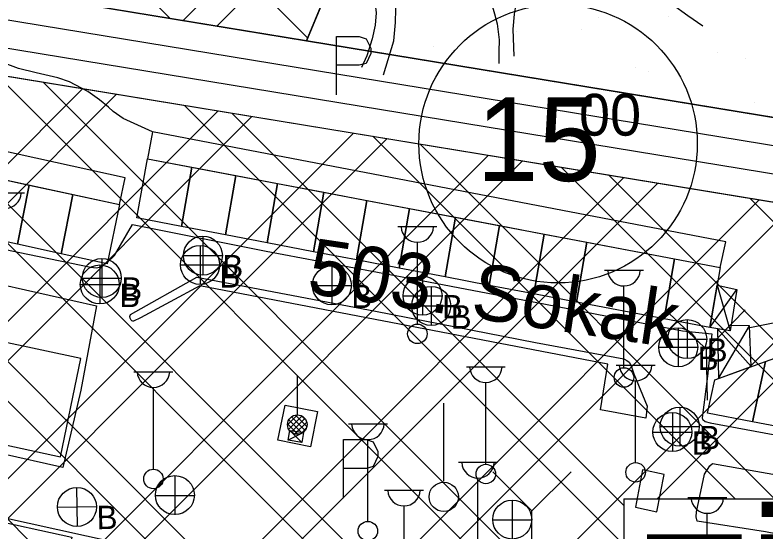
# Model space of a CAD drawing. Extents: x 417995 to 421451, y 4454518 to 4458015.
# Drawn here: x 419824.7 to 419959.6, y 4456060.9 to 4456153.7 of the extents above; entities that cross this region are included whole.
import ezdxf

# ---------------------------------------------------------------- set-up
doc = ezdxf.new("R2010")
doc.units = 0
for name, color, linetype in [('ADAKENARI', 7, 'Continuous'), ('B_Imalat', 7, 'Continuous'), ('B_Sundurma', 7, 'Continuous'), ('KALDIRIM_FAT', 7, 'Continuous'), ('KD_DAIRE', 7, 'Continuous'), ('KD_YGEN', 7, 'Continuous'), ('PL_AYA_PARK_DINLENME', 7, 'Continuous'), ('PL_K_DEPOLAMA', 7, 'Continuous'), ('PL_TOPLU_ISYERI', 7, 'Continuous'), ('S_Bayrak_Diregi', 7, 'Continuous'), ('S_Cad_Sok_Lambasi', 7, 'Continuous'), ('S_GSM_Baz_ist', 7, 'Continuous'), ('S_Otopark', 7, 'Continuous'), ('S_Rogar_Kapagi', 7, 'Continuous'), ('S_Rogar_Kapagi_Buski', 7, 'Continuous'), ('S_Yangin_Vanasi', 7, 'Continuous'), ('Sinir_Tel_bir_taraf', 7, 'Continuous'), ('TRFAT_DEPOLAMA', 7, 'Continuous'), ('TRFAT_PARKALANI', 7, 'Continuous'), ('TRFAT_TOPLUİŞYERLERİ', 7, 'Continuous'), ('Y_Cadde_Yol', 7, 'Continuous'), ('Yol_Kaldirim_kenari_bordurtasi', 7, 'Continuous'), ('Yol_Sose', 7, 'Continuous')]:
    doc.layers.add(name, color=color, linetype=linetype)

msp = doc.modelspace()

# ---------------------------------------------------------------- linework, layer by layer
at = {"layer": 'ADAKENARI'}
for p, q in [((419877.03, 4456149.07), (419946.16, 4456314.89)), ((419776.06, 4456165.64), (419877.03, 4456149.07)), ((419771.34, 4456151.21), (420017.31, 4456110.85)), ((419877.03, 4456149.07), (419969.35, 4456133.92))]:
    msp.add_line(p, q, dxfattribs=at)
at = {"layer": 'B_Imalat'}
for points in [[(419843.42, 4456119.65), (419844.44, 4456124.45), (419796.82, 4456134.91), (419795.72, 4456129.95)], [(419951.33, 4456108.35), (419952.36, 4456112.94), (419849.37, 4456132.69), (419848.49, 4456127.88)], [(419848.49, 4456127.88), (419856.44, 4456126.38), (419854.6, 4456115.71), (419846.53, 4456117.26)], [(419856.44, 4456126.38), (419864.32, 4456124.88), (419862.48, 4456114.21), (419854.6, 4456115.71)], [(419819.3, 4456124.85), (419827.21, 4456123.15), (419825.1, 4456112.52), (419817.19, 4456114.24)], [(419864.32, 4456124.88), (419871.81, 4456123.46), (419869.97, 4456112.77), (419862.48, 4456114.21)], [(419827.21, 4456123.15), (419835.07, 4456121.45), (419832.95, 4456110.81), (419825.1, 4456112.52)], [(419871.81, 4456123.46), (419880.12, 4456121.88), (419878.28, 4456111.19), (419869.97, 4456112.77)], [(419880.12, 4456121.88), (419887.86, 4456120.41), (419886.01, 4456109.71), (419878.28, 4456111.19)], [(419835.07, 4456121.45), (419843.42, 4456119.65), (419841.25, 4456109), (419832.95, 4456110.81)], [(419887.86, 4456120.41), (419895.54, 4456118.95), (419893.69, 4456108.24), (419886.01, 4456109.71)], [(419895.54, 4456118.95), (419903.77, 4456117.38), (419901.92, 4456106.66), (419893.69, 4456108.24)], [(419903.77, 4456117.38), (419911.72, 4456115.88), (419909.86, 4456105.15), (419901.92, 4456106.66)], [(419911.72, 4456115.88), (419919.69, 4456114.36), (419917.84, 4456103.62), (419909.86, 4456105.15)], [(419919.69, 4456114.36), (419927.38, 4456112.9), (419925.53, 4456102.15), (419917.84, 4456103.62)], [(419927.38, 4456112.9), (419943.13, 4456109.91), (419941.27, 4456099.14), (419925.53, 4456102.15)], [(419943.13, 4456109.91), (419951.33, 4456108.35), (419949.47, 4456097.57), (419941.27, 4456099.14)], [(419957.13, 4456080.66), (419959.5, 4456091.5), (419967.65, 4456094.44), (419966.93, 4456089.9), (419967.35, 4456089.82), (419965.02, 4456079.14)], [(419949.06, 4456082.23), (419950.37, 4456088.21), (419959.5, 4456091.5), (419957.13, 4456080.66)], [(419818.97, 4456063.44), (419834.88, 4456059.95), (419832.71, 4456049.03), (419816.79, 4456052.47)]]:
    msp.add_lwpolyline(points, close=True, dxfattribs=at)
at = {"layer": 'B_Sundurma'}
for p, q in [((419949.47, 4456097.57), (419954.33, 4456104.39)), ((419950.78, 4456105.17), (419953.1, 4456097.01)), ((419951.05, 4456088.46), (419956.62, 4456097.87)), ((419950.85, 4456097.36), (419956.91, 4456090.57)), ((419876.49, 4456078.71), (419873.75, 4456077.35)), ((419874.05, 4456079.12), (419876.19, 4456076.94))]:
    msp.add_line(p, q, dxfattribs=at)
for points in [[(419949.47, 4456097.57), (419950.78, 4456105.17), (419954.33, 4456104.39), (419953.1, 4456097.01)], [(419950.85, 4456097.36), (419951.05, 4456088.46), (419956.91, 4456090.57), (419956.62, 4456097.87), (419953.25, 4456097.92), (419953.1, 4456097.01)], [(419874.05, 4456079.12), (419876.49, 4456078.71), (419876.19, 4456076.94), (419873.75, 4456077.35)]]:
    msp.add_lwpolyline(points, close=True, dxfattribs=at)
at = {"layer": 'KALDIRIM_FAT'}
for p, q in [((419764.54, 4456162.46), (420016.91, 4456121.05)), ((419762.96, 4456157.65), (420017.11, 4456115.95))]:
    msp.add_line(p, q, dxfattribs=at)
at = {"layer": 'KD_DAIRE'}
msp.add_circle((419922.22, 4456130.58), 25, dxfattribs=at)
at = {"layer": 'PL_AYA_PARK_DINLENME'}
msp.add_lwpolyline([(419877.03, 4456149.07), (419946.16, 4456314.89), (419962.3, 4456307.28), (419997.77, 4456307.14), (419969.35, 4456133.92)], close=True, dxfattribs=at)
at = {"layer": 'PL_K_DEPOLAMA'}
msp.add_lwpolyline([(419774.25, 4456168.89), (419852.21, 4456355.88), (419856.08, 4456357.37), (419946.16, 4456314.89), (419877.03, 4456149.07), (419776.06, 4456165.64)], close=True, dxfattribs=at)
at = {"layer": 'PL_TOPLU_ISYERI'}
msp.add_lwpolyline([(419771.34, 4456151.21), (420017.31, 4456110.85)], dxfattribs=at)
at = {"layer": 'S_Bayrak_Diregi'}
msp.add_line((419901.67, 4456070.01), (419901.67, 4456084.01), dxfattribs=at)
msp.add_circle((419901.68, 4456067.19), 2.63, dxfattribs=at)
at = {"layer": 'S_Cad_Sok_Lambasi'}
for p, q in [((419819.37, 4456121.78), (419826.37, 4456121.78)), ((419893.44, 4456115.7), (419900.44, 4456115.7)), ((419896.94, 4456098.2), (419896.94, 4456112.88)), ((419930.55, 4456107.86), (419937.55, 4456107.86)), ((419934.05, 4456090.36), (419934.05, 4456105.04)), ((419932.64, 4456090.84), (419939.64, 4456090.84)), ((419846.03, 4456089.65), (419853.03, 4456089.65)), ((419905.74, 4456090.54), (419912.74, 4456090.54)), ((419936.14, 4456073.34), (419936.14, 4456088.01)), ((419849.53, 4456072.15), (419849.53, 4456086.82)), ((419909.24, 4456073.04), (419909.24, 4456087.71)), ((419884.55, 4456080.29), (419891.55, 4456080.29)), ((419888.05, 4456062.79), (419888.05, 4456077.46)), ((419904.33, 4456073.39), (419911.33, 4456073.39)), ((419907.83, 4456055.89), (419907.83, 4456070.57)), ((419891.04, 4456068.39), (419898.04, 4456068.39)), ((419945.51, 4456067.05), (419952.51, 4456067.05)), ((419894.54, 4456050.89), (419894.54, 4456065.56)), ((419949.01, 4456049.55), (419949.01, 4456064.23))]:
    msp.add_line(p, q, dxfattribs=at)
for centre in [(419896.94, 4456096.45), (419934.05, 4456088.61), (419936.14, 4456071.59), (419849.53, 4456070.4), (419909.24, 4456071.29), (419888.05, 4456061.04)]:
    msp.add_circle(centre, 1.75, dxfattribs=at)
for centre in [(419822.87, 4456121.88), (419896.94, 4456115.81), (419934.05, 4456107.97), (419936.14, 4456090.94), (419849.53, 4456089.75), (419909.24, 4456090.64), (419888.05, 4456080.39), (419907.83, 4456073.5), (419894.54, 4456068.49), (419949.01, 4456067.16)]:
    msp.add_arc(centre, 2.93, 183.298, 356.9072, dxfattribs=at)
at = {"layer": 'S_GSM_Baz_ist'}
for p, q in [((419875.38, 4456081.89), (419875.38, 4456088.89)), ((419873.63, 4456080.14), (419875.41, 4456081.89)), ((419873.84, 4456079.33), (419876.18, 4456081.68)), ((419876.78, 4456079.09), (419874.33, 4456081.54)), ((419877.06, 4456079.79), (419875.03, 4456081.85)), ((419876.95, 4456080.87), (419876.11, 4456081.71)), ((419875.45, 4456078.42), (419873.66, 4456080.24)), ((419876.22, 4456078.63), (419873.87, 4456081.01)), ((419874.29, 4456078.81), (419876.71, 4456081.26)), ((419874.96, 4456078.49), (419877.06, 4456080.59)), ((419876.04, 4456078.56), (419876.95, 4456079.51))]:
    msp.add_line(p, q, dxfattribs=at)
msp.add_circle((419875.37, 4456080.16), 1.75, dxfattribs=at)
at = {"layer": 'S_Otopark'}
for points in [[(419882.41, 4456149.83), (419886.51, 4456149.83)], [(419882.41, 4456139.33), (419882.41, 4456149.83)], [(419886.51, 4456149.83), (419887.73, 4456149.41), (419888.57, 4456147.7), (419888.57, 4456146.79), (419887.73, 4456145), (419886.51, 4456144.65)], [(419886.51, 4456144.65), (419882.41, 4456144.65)], [(419883.68, 4456077.48), (419887.78, 4456077.48)], [(419883.68, 4456066.98), (419883.68, 4456077.48)], [(419887.78, 4456077.48), (419889, 4456077.06), (419889.84, 4456075.35), (419889.84, 4456074.44), (419889, 4456072.65), (419887.78, 4456072.3)], [(419887.78, 4456072.3), (419883.68, 4456072.3)]]:
    msp.add_lwpolyline(points, dxfattribs=at)
at = {"layer": 'S_Rogar_Kapagi'}
for p, q in [((419853.43, 4456063.98), (419853.43, 4456070.98)), ((419849.86, 4456067.44), (419856.86, 4456067.44)), ((419914.03, 4456059.6), (419914.03, 4456066.6)), ((419910.46, 4456063.06), (419917.46, 4456063.06))]:
    msp.add_line(p, q, dxfattribs=at)
for centre in [(419853.38, 4456067.5), (419913.98, 4456063.12)]:
    msp.add_circle(centre, 3.5, dxfattribs=at)
at = {"layer": 'S_Rogar_Kapagi_Buski'}
for p, q in [((419858.41, 4456113.99), (419858.41, 4456106.99)), ((419857.91, 4456112.32), (419857.91, 4456105.32)), ((419840.26, 4456109.97), (419840.26, 4456102.97)), ((419854.91, 4456110.49), (419861.91, 4456110.49)), ((419839.9, 4456108.81), (419839.9, 4456101.81)), ((419854.41, 4456108.82), (419861.41, 4456108.82)), ((419881.58, 4456108.65), (419881.58, 4456101.65)), ((419836.76, 4456106.47), (419843.76, 4456106.47)), ((419897.87, 4456106.8), (419897.87, 4456099.8)), ((419836.4, 4456105.31), (419843.4, 4456105.31)), ((419878.08, 4456105.15), (419885.08, 4456105.15)), ((419899.43, 4456104.96), (419899.43, 4456097.96)), ((419894.37, 4456103.3), (419901.37, 4456103.3)), ((419895.93, 4456101.46), (419902.93, 4456101.46)), ((419945.41, 4456099), (419945.41, 4456092)), ((419943.79, 4456097.53), (419943.79, 4456090.53)), ((419941.91, 4456095.5), (419948.91, 4456095.5)), ((419940.29, 4456094.03), (419947.29, 4456094.03)), ((419944.07, 4456083.3), (419944.07, 4456076.3)), ((419942.74, 4456082.32), (419942.74, 4456075.32)), ((419939.24, 4456078.82), (419946.24, 4456078.82)), ((419940.57, 4456079.8), (419947.57, 4456079.8)), ((419835.73, 4456068.88), (419835.85, 4456061.88)), ((419832.29, 4456065.32), (419839.29, 4456065.44))]:
    msp.add_line(p, q, dxfattribs=at)
for centre in [(419858.41, 4456110.49), (419857.91, 4456108.82), (419840.26, 4456106.47), (419839.9, 4456105.31), (419881.58, 4456105.15), (419897.87, 4456103.3), (419899.43, 4456101.46), (419945.41, 4456095.5), (419943.79, 4456094.03), (419944.07, 4456079.8), (419942.74, 4456078.82), (419835.79, 4456065.38)]:
    msp.add_circle(centre, 3.5, dxfattribs=at)
at = {"layer": 'S_Yangin_Vanasi'}
for p, q in [((419948.9, 4456093.63), (419941.78, 4456100.51)), ((419948.9, 4456093.63), (419955.82, 4456100.75)), ((419949.06, 4456084.57), (419948.9, 4456093.63)), ((419917.51, 4456064.7), (419910.51, 4456071.7)), ((419917.51, 4456064.7), (419924.55, 4456071.7)), ((419917.51, 4456055.64), (419917.51, 4456064.7))]:
    msp.add_line(p, q, dxfattribs=at)
at = {"layer": 'Sinir_Tel_bir_taraf'}
for points in [[(419849.37, 4456132.69), (419844.11, 4456135.1), (419842.3, 4456136.33), (419841.45, 4456137.16), (419839.85, 4456138.44), (419837.72, 4456139.94), (419834.46, 4456141.68), (419832.37, 4456142.38), (419828.44, 4456143.27), (419825.32, 4456144.09), (419820.93, 4456145.7), (419817.03, 4456148.38), (419812.61, 4456151.44), (419809.51, 4456152.86), (419805.1, 4456153.98), (419801.66, 4456155.13), (419799.43, 4456156.8), (419797.08, 4456158.2), (419792.72, 4456161.53), (419784.09, 4456165.28), (419773.42, 4456169.24)], [(419956.64, 4456097.56), (419993.12, 4456104.8), (420002.58, 4456103.97)]]:
    msp.add_lwpolyline(points, dxfattribs=at)
msp.add_lwpolyline([(419873.17, 4456083.67), (419879.03, 4456082.48), (419877.75, 4456076.16), (419871.88, 4456077.35)], close=True, dxfattribs=at)
at = {"layer": 'TRFAT_DEPOLAMA'}
for p, q in [((419798.87, 4456227.93), (419877.23, 4456149.56)), ((419792.63, 4456212.96), (419852.49, 4456153.1)), ((419854.88, 4456152.71), (419895.47, 4456193.3)), ((419860.95, 4456151.71), (419890.41, 4456181.17))]:
    msp.add_line(p, q, dxfattribs=at)
at = {"layer": 'TRFAT_PARKALANI'}
for p, q in [((419929.46, 4456153.32), (419929.46, 4456153.32)), ((419941.99, 4456153.43), (419941.99, 4456153.43)), ((419914.69, 4456150.72), (419914.69, 4456150.72)), ((419926.35, 4456151.11), (419926.35, 4456151.11)), ((419899.91, 4456148.11), (419899.91, 4456148.11)), ((419950.89, 4456146.95), (419950.89, 4456146.95)), ((419955.89, 4456145.9), (419955.89, 4456145.9)), ((419936.12, 4456144.34), (419936.12, 4456144.34)), ((419938.52, 4456143.57), (419938.52, 4456143.57)), ((419957.55, 4456137.97), (419957.55, 4456137.97))]:
    msp.add_line(p, q, dxfattribs=at)
at = {"layer": 'TRFAT_TOPLUİŞYERLERİ'}
for p, q in [((419787.46, 4456148.57), (419954, 4455982.02)), ((419795.91, 4456147.18), (419962.72, 4455980.37)), ((419821.29, 4456143.02), (419988.89, 4455975.42)), ((419829.75, 4456141.63), (419934.04, 4456037.34)), ((419836.84, 4456140.46), (419803.44, 4456107.06)), ((419842.92, 4456139.47), (419809.24, 4456105.79)), ((419855.13, 4456137.46), (419934.04, 4456058.55)), ((419867.22, 4456135.48), (419781.29, 4456049.56)), ((419861.14, 4456136.48), (419812.46, 4456087.79)), ((419863.59, 4456136.08), (419934.04, 4456065.63)), ((419885.44, 4456132.49), (419798.72, 4456045.77)), ((419891.51, 4456131.49), (419804.53, 4456044.51)), ((419888.96, 4456131.91), (419954.04, 4456066.84)), ((419897.42, 4456130.52), (419961.11, 4456066.84)), ((419909.74, 4456128.5), (419821.96, 4456040.73)), ((419915.81, 4456127.51), (419827.77, 4456039.47)), ((419922.8, 4456126.36), (420119.13, 4455930.03)), ((419934.03, 4456124.52), (419845.2, 4456035.68)), ((419931.26, 4456124.97), (419995.35, 4456060.89)), ((419940.11, 4456123.52), (419851.01, 4456034.42)), ((419958.33, 4456120.53), (419868.28, 4456030.48)), ((419956.64, 4456120.81), (420007.13, 4456070.31)), ((419964.41, 4456119.53), (419873.42, 4456028.54)), ((419982.63, 4456116.54), (419886.36, 4456020.27)), ((419988.7, 4456115.55), (419939.99, 4456066.84)), ((419815.08, 4456099.73), (419927.83, 4455986.98)), ((419813.81, 4456093.93), (419919.11, 4455988.63)), ((419801.57, 4456084.95), (419852.41, 4456034.12)), ((419934.04, 4456066.84), (419934.04, 4456031.84)), ((419934.04, 4456066.84), (419969.04, 4456066.84))]:
    msp.add_line(p, q, dxfattribs=at)
at = {"layer": 'Yol_Kaldirim_kenari_bordurtasi'}
msp.add_lwpolyline([(419817.65, 4456077.64), (419832.84, 4456074.36), (419836.5, 4456092.04), (419821.6, 4456095.2)], dxfattribs=at)
at = {"layer": 'Yol_Sose'}
for points in [[(419876.57, 4456169.96), (419880.9, 4456166.69), (419885.8, 4456163.78), (419886.68, 4456163.16), (419887.15, 4456162.58), (419888.62, 4456160.2), (419889.09, 4456158), (419889.52, 4456154.04), (419889.37, 4456151.88), (419888.81, 4456149.41), (419887.85, 4456146.34), (419886.92, 4456144.28)], [(419890.84, 4456142.95), (419892.7, 4456149.03), (419893.01, 4456152.34), (419893.16, 4456157.16), (419893.4, 4456158.31), (419893.87, 4456158.95), (419895.13, 4456159.68), (419897.74, 4456159.87), (419900.79, 4456159.81), (419903.04, 4456159.68), (419905.79, 4456159.27), (419907.57, 4456158.93), (419908.48, 4456158.43), (419909.19, 4456157.6), (419909.58, 4456156.86), (419910.29, 4456155.55), (419910.77, 4456153.91), (419911.25, 4456152.07), (419911.62, 4456149.22), (419911.58, 4456147.14), (419911.59, 4456145)], [(419914.3, 4456146.32), (419914.12, 4456151.14), (419914.37, 4456153.84), (419914.61, 4456155.29), (419915.51, 4456156.76), (419920.27, 4456157.93), (419934.38, 4456158.06), (419938.81, 4456157.78), (419942.69, 4456155.62), (419945.54, 4456153.58), (419948.21, 4456151.71)], [(419793.08, 4456117.86), (419825.24, 4456111.11), (419838.3, 4456108.42), (419839.25, 4456108.32), (419839.82, 4456108.39), (419840.2, 4456108.57), (419840.5, 4456108.81), (419841.22, 4456109.28), (419842.54, 4456110.49), (419845.76, 4456116.05), (419869.79, 4456111.28), (419895.15, 4456106.52), (419919.97, 4456101.8), (419944.59, 4456096.99), (419949.85, 4456096.42), (419949.08, 4456088.87), (419948.11, 4456081.35), (419948.16, 4456081.1), (419948.19, 4456081.07), (419948.62, 4456080.74), (419949.53, 4456080.48), (419971.2, 4456076.47)], [(419789.47, 4456082.03), (419786.05, 4456082.64), (419784.92, 4456083.23), (419784.4, 4456084.3), (419785.52, 4456091.41), (419789.91, 4456111.99), (419818.01, 4456106.27), (419839.28, 4456101.46), (419836.51, 4456086.33), (419833.28, 4456072.48), (419799.6, 4456080.02), (419789.47, 4456082.03)], [(419845.4, 4456099.89), (419857.33, 4456106.61), (419889.43, 4456100.53), (419918.14, 4456094.88), (419934.04, 4456091.97), (419934.55, 4456091.68), (419934.98, 4456091.38), (419935.34, 4456090.69), (419935.83, 4456089.28), (419938.23, 4456083.44), (419937.97, 4456081.31), (419929.83, 4456082.78), (419931.13, 4456091.03), (419857.89, 4456105.09), (419847.19, 4456099.34)], [(419847.19, 4456099.34), (419845.98, 4456098.74), (419845.84, 4456098.72), (419845.68, 4456098.79), (419845.56, 4456098.92), (419845.42, 4456099.13), (419845.35, 4456099.24), (419845.33, 4456099.35), (419845.31, 4456099.45), (419845.32, 4456099.57), (419845.4, 4456099.89)], [(419768.51, 4456075.57), (419816.86, 4456064.73), (419862.73, 4456054.65), (419888.23, 4456049.33), (419888.26, 4456049.33), (419889.72, 4456049.54), (419910.97, 4456058.76), (419938.94, 4456053.33), (419935.74, 4456035.79), (419931.94, 4456015.16), (419929.85, 4456005.36), (419934.81, 4456004.36), (419935.59, 4456008.29), (420020.93, 4455992.2)], [(419939.96, 4456064.52), (419941.29, 4456071.22), (419937.36, 4456072.02), (419936.11, 4456065.33), (419939.96, 4456064.52)], [(419986.61, 4456055.62), (419959.49, 4456060.9), (419947.2, 4456062.85), (419946.99, 4456063.58), (419947.09, 4456064.5), (419948.53, 4456071.26), (419949.48, 4456072.75)], [(419949.48, 4456072.75), (419949.93, 4456073.15), (419971.28, 4456069.38)]]:
    msp.add_lwpolyline(points, dxfattribs=at)

# ---------------------------------------------------------------- texts
at = {"layer": 'KD_YGEN'}
for s, height, p in [('00', 7.5, (419925.97, 4456132.03)), ('15', 15, (419907.56, 4456123.88))]:
    msp.add_text(s, height=height, dxfattribs=at).set_placement(p)
at = {"layer": 'S_Rogar_Kapagi_Buski'}
for p in [(419861.91, 4456106.42), (419861.41, 4456104.75), (419843.76, 4456102.4), (419843.4, 4456101.24), (419885.08, 4456101.08), (419901.37, 4456099.23), (419902.93, 4456097.39), (419948.91, 4456091.43), (419947.29, 4456089.96), (419947.57, 4456075.73), (419946.24, 4456074.75)]:
    msp.add_text('B', height=4.2, dxfattribs=at).set_placement(p)
msp.add_text('B', height=4.2, rotation=1, dxfattribs=at).set_placement((419839.36, 4456061.37))
at = {"layer": 'TRFAT_TOPLUİŞYERLERİ'}
msp.add_text('Tİ', height=22.5, dxfattribs=at).set_placement((419937.52, 4456037.95))
at = {"layer": 'Y_Cadde_Yol'}
msp.add_text('503. Sokak', height=10, rotation=351.4747, dxfattribs=at).set_placement((419876.87, 4456103.79))

doc.saveas('drawing.dxf')
